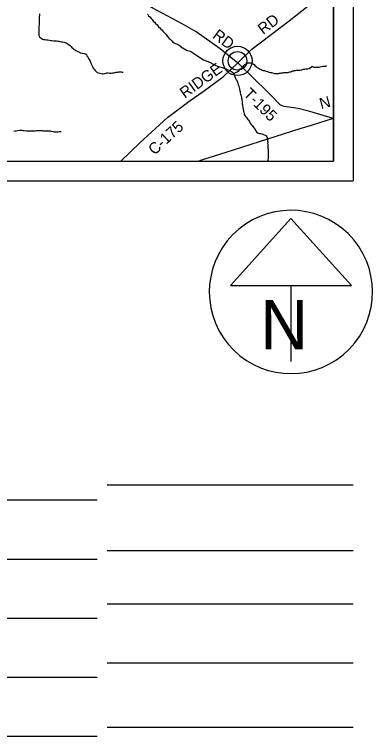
# Model space of a CAD drawing. Extents: x 36.7 to 70.7, y 0 to 22.
# Drawn here: x 43.973 to 45.793, y 11.174 to 14.842 of the extents above; entities that cross this region are included whole.
import ezdxf

# ---------------------------------------------------------------- set-up
doc = ezdxf.new("R2010")
doc.units = 0
for name, color, linetype in [('GM_X_County_Road', 7, 'Continuous'), ('GM_X_County_Road_Text', 7, 'Continuous'), ('GM_X_Minor_River', 7, 'Continuous'), ('GM_X_Rail_Line', 7, 'Continuous'), ('GM_X_Rail_Line_Text', 7, 'Continuous'), ('GM_X_Township_Road', 7, 'Continuous'), ('GM_X_Township_Road_Text', 7, 'Continuous'), ('GM_X_Unincorporated', 7, 'Continuous'), ('GM_X_Unincorporated_Location', 7, 'Continuous'), ('SH_Data', 7, 'Continuous')]:
    doc.layers.add(name, color=color, linetype=linetype)

msp = doc.modelspace()

# ---------------------------------------------------------------- linework, layer by layer
at = {"layer": 'GM_X_County_Road'}
msp.add_lwpolyline([(44.5137, 14.0969), (44.61, 14.1895), (44.7503, 14.3191), (44.8652, 14.405), (44.9312, 14.4499), (45.0351, 14.527), (45.1075, 14.5955), (45.18, 14.6649), (45.3691, 14.8101), (45.4651, 14.8861), (45.5652, 14.9689), (45.5934, 14.9928)], dxfattribs=at)
at = {"layer": 'GM_X_Minor_River'}
for points in [[(44.1, 14.8451), (44.0995, 14.8398), (44.0983, 14.828), (44.0985, 14.817), (44.0984, 14.8098), (44.098, 14.8011), (44.0983, 14.795), (44.0978, 14.7901), (44.0977, 14.7813), (44.0975, 14.7582), (44.097, 14.7517), (44.0969, 14.7419), (44.0972, 14.7365), (44.0979, 14.732), (44.0998, 14.7274), (44.1088, 14.7209), (44.1156, 14.7162), (44.1212, 14.7146), (44.1269, 14.7142), (44.1353, 14.713), (44.1421, 14.7125), (44.1516, 14.7113), (44.1572, 14.7101), (44.1622, 14.7093), (44.1735, 14.708), (44.1796, 14.7076), (44.1875, 14.7075), (44.1936, 14.7067), (44.1985, 14.7055), (44.2042, 14.705), (44.2114, 14.7034), (44.2167, 14.7026), (44.2254, 14.7006), (44.2315, 14.6994), (44.2364, 14.6971), (44.2413, 14.6948), (44.248, 14.6898), (44.2555, 14.6832)], [(44.6485, 14.8445), (44.6548, 14.835), (44.6604, 14.8303), (44.6672, 14.8204), (44.6732, 14.8165), (44.6795, 14.8066), (44.6852, 14.8024), (44.6911, 14.794), (44.6983, 14.7886)], [(44.6983, 14.7886), (44.705, 14.7794), (44.7106, 14.7751), (44.717, 14.7663), (44.7215, 14.7629), (44.7267, 14.7567), (44.7324, 14.7518), (44.7369, 14.746), (44.744, 14.7406), (44.7496, 14.7318), (44.7586, 14.7203), (44.7638, 14.7165), (44.7687, 14.7104), (44.7732, 14.7069), (44.7792, 14.7), (44.7841, 14.6977), (44.7917, 14.6946), (44.7973, 14.6918), (44.8026, 14.6895), (44.8098, 14.6849), (44.815, 14.6825), (44.8218, 14.6745), (44.8278, 14.6718), (44.8346, 14.6668), (44.8399, 14.6648), (44.8474, 14.6605), (44.8527, 14.6594), (44.8595, 14.6562), (44.8659, 14.6547), (44.8735, 14.6523), (44.8784, 14.6485), (44.8844, 14.6427), (44.9337, 14.6107)], [(44.2555, 14.6832), (44.2604, 14.679), (44.2653, 14.674), (44.2698, 14.6702), (44.2751, 14.6655), (44.2841, 14.659), (44.289, 14.6563), (44.2943, 14.6536), (44.303, 14.6497), (44.3094, 14.6473), (44.3196, 14.6449), (44.3272, 14.6437), (44.3325, 14.6425), (44.3389, 14.6383), (44.3415, 14.6322), (44.3459, 14.6264), (44.347, 14.6196), (44.353, 14.6131), (44.356, 14.607), (44.3593, 14.5993), (44.3615, 14.594), (44.3637, 14.5879), (44.3689, 14.5772), (44.373, 14.5681), (44.3778, 14.5635), (44.3831, 14.5573), (44.3887, 14.552), (44.394, 14.5477), (44.4061, 14.543), (44.414, 14.5411), (44.4201, 14.5402), (44.4246, 14.5406), (44.4322, 14.542), (44.4425, 14.5446), (44.4497, 14.5452), (44.4565, 14.544), (44.4645, 14.5439), (44.4717, 14.5454), (44.4804, 14.546), (44.4896, 14.5482), (44.4983, 14.5489), (44.504, 14.5496), (44.5154, 14.5495), (44.5203, 14.549), (44.5249, 14.549)], [(44.9337, 14.6107), (44.972, 14.5959), (44.9758, 14.5925), (44.988, 14.5869), (44.9929, 14.5839), (44.9971, 14.5816), (45.0009, 14.5801), (45.0055, 14.5782), (45.0093, 14.5771), (45.0135, 14.576), (45.0241, 14.5734), (45.0306, 14.5715), (45.0363, 14.5696), (45.0401, 14.5681), (45.0439, 14.5666), (45.0488, 14.5648), (45.053, 14.5625), (45.0576, 14.561), (45.0667, 14.5573), (45.0716, 14.5546), (45.0754, 14.552), (45.0796, 14.5482), (45.0854, 14.5402), (45.0896, 14.5346), (45.0934, 14.5255), (45.0953, 14.5217), (45.0965, 14.5179), (45.0984, 14.513), (45.1007, 14.5088), (45.1046, 14.5012), (45.1061, 14.497), (45.1076, 14.4932), (45.1096, 14.486), (45.1107, 14.4822), (45.1127, 14.4758), (45.115, 14.4694), (45.1165, 14.4644), (45.1173, 14.4591), (45.1181, 14.4549), (45.1196, 14.447), (45.12, 14.4432), (45.1216, 14.4367), (45.1231, 14.4322), (45.1243, 14.428), (45.1262, 14.4204), (45.1266, 14.4162), (45.1282, 14.4113), (45.1289, 14.406), (45.1301, 14.3988), (45.1305, 14.3927), (45.1309, 14.3878), (45.1313, 14.3832), (45.1325, 14.3775), (45.1341, 14.3711), (45.1356, 14.3581), (45.1372, 14.3498), (45.138, 14.346), (45.1395, 14.3384), (45.1407, 14.3339), (45.143, 14.3285), (45.1484, 14.3214), (45.1518, 14.3176), (45.156, 14.3134), (45.1594, 14.3085), (45.1625, 14.3043), (45.1667, 14.2979), (45.1702, 14.2903), (45.1755, 14.2831), (45.1805, 14.2774), (45.1843, 14.2725), (45.1896, 14.265), (45.1946, 14.2589), (45.1988, 14.2521), (45.2011, 14.2475), (45.2042, 14.2426), (45.211, 14.2388), (45.2183, 14.237), (45.2239, 14.2366), (45.23, 14.2355), (45.2353, 14.234), (45.2422, 14.231), (45.2479, 14.2284), (45.2525, 14.225), (45.2555, 14.2201), (45.2575, 14.2144), (45.2582, 14.2094), (45.259, 14.2034), (45.2594, 14.198), (45.2598, 14.1931), (45.2595, 14.1874), (45.2603, 14.1817), (45.2607, 14.176), (45.2607, 14.1703), (45.2611, 14.1623), (45.2615, 14.1578), (45.2616, 14.1513), (45.262, 14.1434), (45.2624, 14.1358), (45.2625, 14.1232), (45.2618, 14.1149), (45.2618, 14.1095)], [(45.0837, 14.5426), (45.0945, 14.546), (45.0983, 14.5468), (45.1047, 14.5495), (45.1104, 14.5537), (45.1141, 14.5567), (45.1187, 14.5609), (45.1225, 14.5651), (45.1274, 14.5697), (45.1311, 14.5739), (45.1345, 14.5777), (45.1394, 14.5827), (45.144, 14.5869), (45.1485, 14.5903), (45.1538, 14.5934), (45.1591, 14.5957), (45.1644, 14.5965), (45.1701, 14.5965), (45.1743, 14.5954), (45.1808, 14.592), (45.1861, 14.5905), (45.1907, 14.5871), (45.1949, 14.5829), (45.201, 14.578), (45.2071, 14.5727), (45.2166, 14.5671), (45.2219, 14.5641), (45.2261, 14.5622), (45.2326, 14.5592), (45.2367, 14.5577), (45.2413, 14.5566), (45.2462, 14.5551), (45.2508, 14.5536), (45.2569, 14.5521), (45.2622, 14.5506), (45.2675, 14.5487), (45.2725, 14.5476), (45.2786, 14.5465), (45.2907, 14.5435), (45.2949, 14.5424), (45.2987, 14.542), (45.3086, 14.5421), (45.3143, 14.5425), (45.3203, 14.5433), (45.3245, 14.5441), (45.3302, 14.5448), (45.3366, 14.5456), (45.3419, 14.5464), (45.3473, 14.5468), (45.3533, 14.5472), (45.359, 14.5473), (45.3632, 14.5477), (45.367, 14.5488), (45.3723, 14.5496), (45.3776, 14.5511), (45.3825, 14.5531), (45.3882, 14.555), (45.392, 14.5558), (45.3966, 14.5566), (45.4015, 14.5573), (45.4068, 14.5581), (45.4148, 14.5585), (45.4189, 14.5589), (45.4227, 14.559), (45.4292, 14.5597), (45.433, 14.5605), (45.4368, 14.5621), (45.4421, 14.5632), (45.4478, 14.5644), (45.4531, 14.5648), (45.4572, 14.5652), (45.4637, 14.5649), (45.4709, 14.5672), (45.4766, 14.5721), (45.4819, 14.5752), (45.486, 14.5783), (45.491, 14.5764), (45.4948, 14.5745), (45.4993, 14.5738), (45.5062, 14.5734), (45.5103, 14.5738), (45.5149, 14.5735), (45.5206, 14.5735), (45.5267, 14.575), (45.5339, 14.5773), (45.5392, 14.5785), (45.5437, 14.5789), (45.5494, 14.5789), (45.5532, 14.5786), (45.5589, 14.582)], [(43.9695, 14.2486), (43.976, 14.25), (43.9809, 14.2511), (43.9893, 14.2529), (43.9995, 14.2532), (44.0052, 14.2531), (44.0105, 14.2531), (44.0166, 14.2526), (44.0227, 14.2518), (44.0348, 14.2509), (44.0428, 14.2512), (44.0519, 14.2504), (44.0621, 14.2502), (44.0708, 14.2498), (44.0784, 14.2501), (44.0853, 14.2515), (44.0928, 14.2526), (44.1016, 14.2525), (44.108, 14.252), (44.1137, 14.2516), (44.119, 14.2508), (44.1254, 14.2507), (44.1342, 14.2506), (44.1425, 14.2509), (44.149, 14.2512), (44.1539, 14.2508), (44.1592, 14.2492), (44.1694, 14.2468), (44.1747, 14.246), (44.1819, 14.2455), (44.1876, 14.2455), (44.1933, 14.245), (44.2005, 14.2469), (44.2051, 14.2476), (44.2096, 14.2479)], [(45.2618, 14.1095), (45.2614, 14.1038), (45.2615, 14.0985), (45.2611, 14.0969)]]:
    msp.add_lwpolyline(points, dxfattribs=at)
at = {"layer": 'GM_X_Rail_Line'}
msp.add_lwpolyline([(44.9061, 14.0969), (44.9309, 14.1048), (45.0486, 14.1428), (45.2178, 14.1966), (45.4244, 14.2616), (45.4822, 14.2799), (45.5252, 14.2932), (45.5893, 14.3137), (45.5934, 14.315)], dxfattribs=at)
at = {"layer": 'GM_X_Township_Road'}
for points in [[(41.174, 14.9671), (41.1522, 14.4699), (41.1418, 14.0969), (45.5934, 14.0969), (45.5934, 19.8832)], [(45.0999, 14.6015), (45.0182, 14.6667), (44.8966, 14.7532), (44.8251, 14.7935), (44.6722, 14.8746), (44.5866, 14.9303), (44.2818, 15.3016)], [(45.5934, 14.3121), (45.592, 14.3132), (45.4734, 14.3483), (45.4139, 14.3643), (45.3444, 14.3747), (45.3243, 14.3807), (45.2751, 14.4312), (45.1703, 14.5345), (45.1316, 14.5716), (45.1075, 14.5955), (45.0999, 14.6015)]]:
    msp.add_lwpolyline(points, dxfattribs=at)
at = {"layer": 'GM_X_Unincorporated'}
for radius in [0.0744, 0.0472]:
    msp.add_circle((45.1064, 14.606), radius, dxfattribs=at)
at = {"layer": 'GM_X_Unincorporated_Location'}
msp.add_line((45.1064, 14.606), (45.1064, 14.606), dxfattribs=at)
at = {"layer": 'SH_Data'}
for p, q in [((45.6934, 20.9969), (45.6934, 13.9969)), ((45.5934, 20.8969), (45.5934, 14.0969)), ((38.7934, 14.0969), (45.5934, 14.0969)), ((38.6934, 13.9969), (45.6934, 13.9969)), ((45.3779, 13.806), (45.0703, 13.4647)), ((45.6855, 13.4647), (45.3779, 13.806)), ((45.0703, 13.4647), (45.6855, 13.4647)), ((45.3779, 13.4647), (45.3779, 13.078)), ((45.3779, 13.4322), (45.3779, 13.4322)), ((45.3779, 13.4322), (45.3779, 13.4322)), ((44.4434, 12.4522), (45.6934, 12.4522)), ((44.3934, 12.3736), (41.1871, 12.3736)), ((45.6934, 12.1177), (44.4434, 12.1177)), ((44.3934, 12.0736), (40.6829, 12.0736)), ((45.6934, 11.846), (44.4434, 11.846)), ((44.3934, 11.7736), (40.3126, 11.7736)), ((45.6934, 11.546), (44.4434, 11.546)), ((44.3934, 11.4736), (40.0222, 11.4736)), ((45.6934, 11.2192), (44.4434, 11.2192)), ((44.3934, 11.1736), (41.4387, 11.1736))]:
    msp.add_line(p, q, dxfattribs=at)
msp.add_arc((45.3779, 13.4322), 0.4148, 129.7798, 129.7633, dxfattribs=at)

# ---------------------------------------------------------------- texts
at = {"layer": 'GM_X_County_Road_Text'}
for s, rotation, p in [('RD', 37.6583, (45.2368, 14.7371)), ('RIDGE', 35.8092, (44.8387, 14.4128)), ('C-175', 42.6625, (44.6849, 14.1243))]:
    msp.add_text(s, height=0.05682, rotation=rotation, dxfattribs=at).set_placement(p)
at = {"layer": 'GM_X_Rail_Line_Text'}
msp.add_text('N', height=0.0566, rotation=15.1177, dxfattribs=at).set_placement((45.5313, 14.36))
at = {"layer": 'GM_X_Township_Road_Text'}
for s, rotation, p in [('RD', 323.4237, (44.9752, 14.7258)), ('T-195', 315.1956, (45.1328, 14.4334))]:
    msp.add_text(s, height=0.05682, rotation=rotation, dxfattribs=at).set_placement(p)
at = {"layer": 'SH_Data'}
msp.add_text('N', height=0.25, dxfattribs=at).set_placement((45.2226, 13.1409))

doc.saveas('drawing.dxf')
